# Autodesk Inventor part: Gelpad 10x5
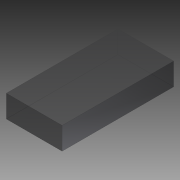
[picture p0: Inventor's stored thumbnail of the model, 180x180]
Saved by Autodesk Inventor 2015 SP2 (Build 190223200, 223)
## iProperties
Created: 2015-08
Part Number: Gelpad 10x5
Material: Gummi, Silikon
Document SubType Name: Modeling
Designer: ryll
Mass: 0.125 g
Surface Area: 1.6 cm^2
Volume: 0.1 cm^3
Density: 1.25 g/cm^3
Appearance: Gummi - schwarz - Version 1.1
Author: ryll
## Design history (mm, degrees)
sketch "Skizze1"
  geometry: L1 (-2.5, 5)-(2.5, 5); L2 (2.5, 5)-(2.5, -5); L3 (2.5, -5)-(-2.5, -5); L4 (-2.5, -5)-(-2.5, 5); L5 (-3.5, 0)-(3.5, 0) reference; L6 (0, 7)-(0, -7) reference; 1 further point
  constraints: 8 end point, 2 parallel, 1 horizontal, 1 perpendicular, 2 other
  dimensions: "d0" = 5 distance of L1.start L1.end; "d1" = 10 distance of L1.end L2.end
extrude "Extrusion1" new body sketch "Skizze1" distance "d2" = 2; taper "d3" = 0 deg
node "Volumenkörper1"
